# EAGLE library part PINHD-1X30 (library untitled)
PIN HEADER
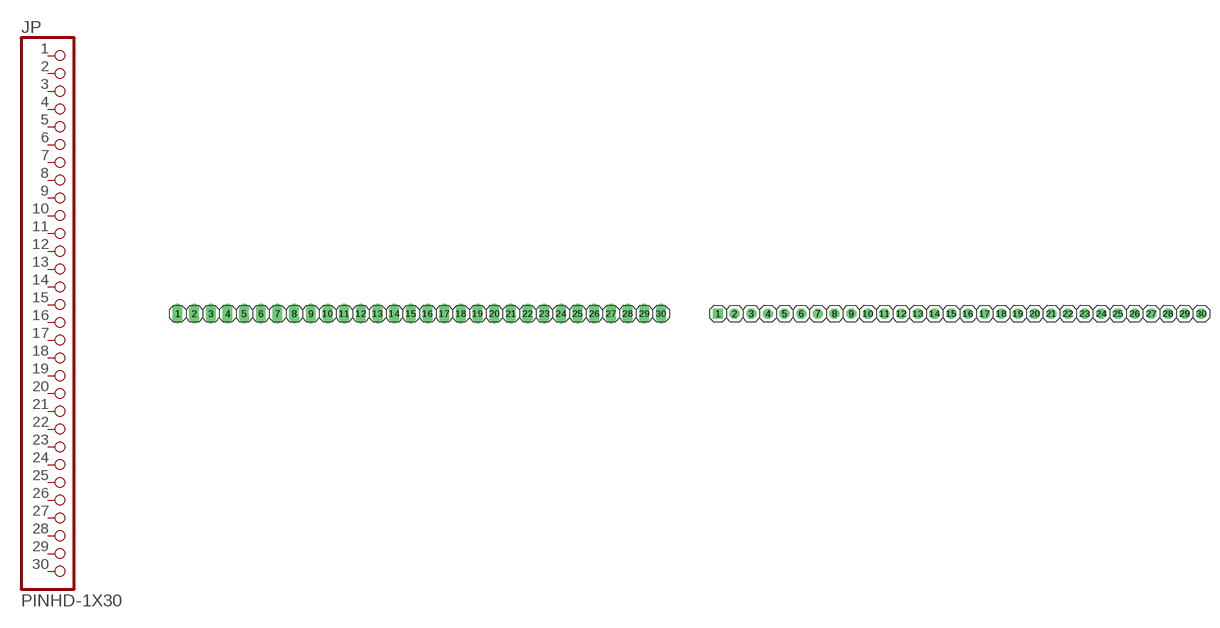
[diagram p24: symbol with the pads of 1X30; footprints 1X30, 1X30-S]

Designator prefix JP

## PINHD-1X30_2.54  [1X30]
1  1  pas
2  2  pas
3  3  pas
4  4  pas
5  5  pas
6  6  pas
7  7  pas
8  8  pas
9  9  pas
10  10  pas
11  11  pas
12  12  pas
13  13  pas
14  14  pas
15  15  pas
16  16  pas
17  17  pas
18  18  pas
19  19  pas
20  20  pas
21  21  pas
22  22  pas
23  23  pas
24  24  pas
25  25  pas
26  26  pas
27  27  pas
28  28  pas
29  29  pas
30  30  pas

## PINHD-1X30_2.54-S  [1X30-S]
Pads as for 1X30

## PINHD-1X30_2.00  [1X30M]
Pads as for 1X30

## PINHD-1X30_2.54-90°  [1X30/90]
Pads as for 1X30

## PINHD-1X30_2.54-90°-S  [1X30/90-S]
Pads as for 1X30

## PINHD-1X30_2.54-SMD  [1X30SMD]
Pads as for 1X30

## PINHD-1X30_2.54-SMD-90°  [1X30SMD/90]
Pads as for 1X30

## Footprint 1X30 (pad centres in mm)
PIN HEADER - 2.54
drill 1.016 long: 1 -36.83,0; 2 -34.29,0; 3 -31.75,0; 4 -29.21,0; 5 -26.67,0; 6 -24.13,0; 7 -21.59,0; 8 -19.05,0; 9 -16.51,0; 10 -13.97,0; 11 -11.43,0; 12 -8.89,0; 13 -6.35,0; 14 -3.81,0; 15 -1.27,0; 16 1.27,0; 17 3.81,0; 18 6.35,0; 19 8.89,0; 20 11.43,0; 21 13.97,0; 22 16.51,0; 23 19.05,0; 24 21.59,0; 25 24.13,0; 26 26.67,0; 27 29.21,0; 28 31.75,0; 29 34.29,0; 30 36.83,0

## Footprint 1X30-S (pad centres in mm)
PIN HEADER - 2.54
drill 1.016 square: 1 -36.83,0
drill 1.016 octagon: 2 -34.29,0; 3 -31.75,0; 4 -29.21,0; 5 -26.67,0; 6 -24.13,0; 7 -21.59,0; 8 -19.05,0; 9 -16.51,0; 10 -13.97,0; 11 -11.43,0; 12 -8.89,0; 13 -6.35,0; 14 -3.81,0; 15 -1.27,0; 16 1.27,0; 17 3.81,0; 18 6.35,0; 19 8.89,0; 20 11.43,0; 21 13.97,0; 22 16.51,0; 23 19.05,0; 24 21.59,0; 25 24.13,0; 26 26.67,0; 27 29.21,0; 28 31.75,0; 29 34.29,0; 30 36.83,0

## Footprint 1X30M (pad centres in mm)
PIN HEADER - 2
drill 0.914 square: 1 -29,0
drill 0.914 round: 2 -27,0; 3 -25,0; 4 -23,0; 5 -21,0; 6 -19,0; 7 -17,0; 8 -15,0; 9 -13,0; 10 -11,0; 11 -9,0; 12 -7,0; 13 -5,0; 14 -3,0; 15 -1,0; 16 1,0; 17 3,0; 18 5,0; 19 7,0; 20 9,0; 21 11,0; 22 13,0; 23 15,0; 24 17,0; 25 19,0; 26 21,0; 27 23,0; 28 25,0; 29 27,0; 30 29,0

## Footprint 1X30/90 (pad centres in mm)
PIN HEADER - 2.54 90°
drill 1.016 long: 1 -24.13,-3.81; 2 -21.59,-3.81; 3 -19.05,-3.81; 4 -16.51,-3.81; 5 -13.97,-3.81; 6 -11.43,-3.81; 7 -8.89,-3.81; 8 -6.35,-3.81; 9 -3.81,-3.81; 10 -1.27,-3.81; 11 1.27,-3.81; 12 3.81,-3.81; 13 6.35,-3.81; 14 8.89,-3.81; 15 11.43,-3.81; 16 13.97,-3.81; 17 16.51,-3.81; 18 19.05,-3.81; 19 21.59,-3.81; 20 24.13,-3.81; 21 26.67,-3.81; 22 29.21,-3.81; 23 31.75,-3.81; 24 34.29,-3.81; 25 36.83,-3.81; 26 39.37,-3.81; 27 41.91,-3.81; 28 44.45,-3.81; 29 46.99,-3.81; 30 49.53,-3.81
